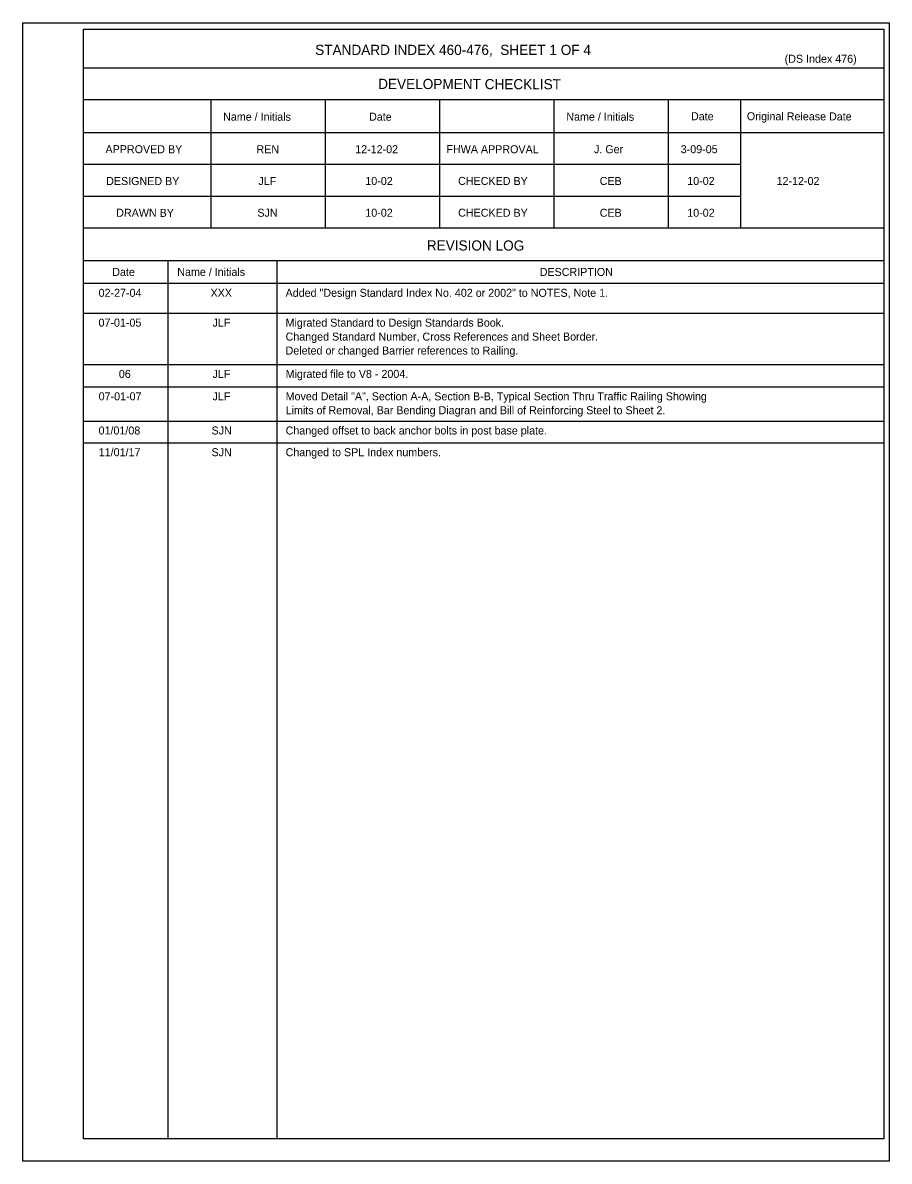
# Model space of a CAD drawing. Extents: x 21516.9 to 21589, y 56155.1 to 56195.
# Drawn here: x 21567.19 to 21589, y 56162.34 to 56191 of the extents above; entities that cross this region are included whole.
import ezdxf

# ---------------------------------------------------------------- set-up
doc = ezdxf.new("R2010")
doc.units = 0
for name, color, linetype in [('PlotBorder_dp', 7, 'Continuous'), ('SheetBorder_dp', 7, 'Continuous'), ('SheetLines_dp', 7, 'Continuous')]:
    doc.layers.add(name, color=color, linetype=linetype)

msp = doc.modelspace()

# ---------------------------------------------------------------- linework, layer by layer
at = {"layer": 'PlotBorder_dp'}
for p, q in [((21568.718, 56183.689), (21588.865, 56183.689)), ((21568.719, 56182.398), (21588.865, 56182.398)), ((21568.719, 56181.834), (21588.865, 56181.834)), ((21568.719, 56180.973), (21588.865, 56180.973)), ((21568.719, 56180.427), (21588.865, 56180.427)), ((21567.188, 56162.336), (21567.188, 56162.336))]:
    msp.add_line(p, q, dxfattribs=at)
msp.add_lwpolyline([(21567.188, 56191.002), (21589.001, 56191.002), (21589.001, 56162.336), (21567.188, 56162.336)], close=True, dxfattribs=at)
at = {"layer": 'SheetLines_dp'}
for p, q in [((21588.865, 56189.859), (21568.718, 56189.859)), ((21588.865, 56189.059), (21568.718, 56189.059)), ((21571.918, 56189.059), (21571.918, 56185.831)), ((21574.798, 56189.059), (21574.798, 56185.831)), ((21577.678, 56189.059), (21577.678, 56185.831)), ((21580.558, 56189.059), (21580.558, 56185.831)), ((21583.438, 56189.059), (21583.438, 56185.831)), ((21585.253, 56189.059), (21585.253, 56185.831)), ((21588.865, 56188.231), (21568.718, 56188.231)), ((21585.253, 56187.431), (21568.718, 56187.431)), ((21585.253, 56186.631), (21568.718, 56186.631)), ((21588.865, 56185.831), (21568.718, 56185.831)), ((21588.865, 56185.004), (21568.718, 56185.004)), ((21570.838, 56185.004), (21570.838, 56162.897)), ((21573.581, 56185.004), (21573.581, 56162.897)), ((21588.865, 56184.44), (21568.718, 56184.44))]:
    msp.add_line(p, q, dxfattribs=at)
msp.add_lwpolyline([(21568.718, 56190.84), (21588.865, 56190.84), (21588.865, 56162.897), (21568.718, 56162.897)], close=True, dxfattribs=at)

# ---------------------------------------------------------------- texts
at = {"layer": 'SheetBorder_dp'}
for s, height, p in [('STANDARD INDEX 460-476,  SHEET 1 OF 4', 0.256, (21574.548, 56190.192)), ('(DS Index 476)', 0.2016, (21586.368, 56189.995)), ('REN', 0.2016, (21573.07, 56187.718)), ('12-12-02', 0.2016, (21575.557, 56187.718)), ('J. Ger', 0.2016, (21581.568, 56187.718)), ('3-09-05', 0.2016, (21583.752, 56187.718)), ('JLF', 0.2016, (21573.118, 56186.918)), ('10-02', 0.2016, (21575.812, 56186.918)), ('CEB', 0.2016, (21581.712, 56186.918)), ('10-02', 0.2016, (21583.916, 56186.918)), ('12-12-02', 0.2016, (21586.165, 56186.918)), ('SJN', 0.2016, (21573.093, 56186.118)), ('10-02', 0.2016, (21575.812, 56186.118)), ('CEB', 0.2016, (21581.712, 56186.118)), ('10-02', 0.2016, (21583.916, 56186.118)), ('DESCRIPTION', 0.2016, (21580.202, 56184.627)), ('02-27-04', 0.2016, (21569.097, 56184.102)), ('XXX', 0.2016, (21571.915, 56184.102)), ('Added "Design Standard Index No. 402 or 2002" to NOTES, Note 1. ', 0.2016, (21573.804, 56184.102)), ('07-01-05', 0.2016, (21569.094, 56183.351)), ('JLF', 0.2016, (21571.965, 56183.351)), ('Migrated Standard to Design Standards Book.', 0.2016, (21573.804, 56183.351)), ('Changed Standard Number, Cross References and Sheet Border.', 0.2016, (21573.804, 56182.999)), ('Deleted or changed Barrier references to Railing.', 0.2016, (21573.804, 56182.648)), ('06', 0.2016, (21569.606, 56182.06)), ('JLF', 0.2016, (21571.965, 56182.06)), ('Migrated file to V8 - 2004.', 0.2016, (21573.805, 56182.06)), ('07-01-07', 0.2016, (21569.098, 56181.496)), ('JLF', 0.2016, (21571.965, 56181.496)), ('Moved Detail "A", Section A-A, Section B-B, Typical Section Thru Traffic Railing Showing ', 0.2016, (21573.805, 56181.496)), ('Limits of Removal, Bar Bending Diagran and Bill of Reinforcing Steel to Sheet 2.', 0.2016, (21573.805, 56181.145)), ('01/01/08', 0.2016, (21569.096, 56180.635)), ('SJN', 0.2016, (21571.94, 56180.635)), ('Changed offset to back anchor bolts in post base plate.', 0.2016, (21573.805, 56180.635)), ('11/01/17', 0.2016, (21569.1, 56180.088)), ('SJN', 0.2016, (21571.94, 56180.088)), ('Changed to SPL Index numbers.', 0.2016, (21573.805, 56180.088))]:
    msp.add_text(s, height=height, dxfattribs=at).set_placement(p)
for s, height, p in [('DEVELOPMENT CHECKLIST', 0.256, (21576.134, 56189.336)), ('Name / Initials', 0.2016, (21572.231, 56188.538)), ('Date', 0.2016, (21575.905, 56188.537)), ('Name / Initials', 0.2016, (21580.871, 56188.538)), ('Date', 0.2016, (21584.01, 56188.548)), ('Original Release Date', 0.2016, (21585.417, 56188.548)), ('APPROVED BY', 0.2016, (21569.27, 56187.72)), ('FHWA APPROVAL', 0.2016, (21577.853, 56187.72)), ('DESIGNED BY', 0.2016, (21569.287, 56186.918)), ('CHECKED BY', 0.2016, (21578.148, 56186.92)), ('DRAWN BY', 0.2016, (21569.54, 56186.118)), ('CHECKED BY', 0.2016, (21578.148, 56186.12)), ('REVISION LOG', 0.256, (21577.359, 56185.27)), ('Name / Initials', 0.2016, (21571.077, 56184.629)), ('Date', 0.2016, (21569.44, 56184.627))]:
    msp.add_text(s, height=height, rotation=359.8756, dxfattribs=at).set_placement(p)

doc.saveas('drawing.dxf')
